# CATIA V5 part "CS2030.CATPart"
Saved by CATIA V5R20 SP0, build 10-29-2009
Part number: CS2030
Revision: 5
Definition: design
Nomenclature: CS2030
Source: made
Description: NOT SPECIFIED
Bounding box of the stored display mesh (mm): x -29 to 29, y -29 to 29, z -55 to 15
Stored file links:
  C:\Users\Raffaele\Desktop\3D X SITO CF\BOLEX\20-TILTED COLUMN SUPPORT\CS2030.CATPart
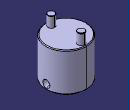
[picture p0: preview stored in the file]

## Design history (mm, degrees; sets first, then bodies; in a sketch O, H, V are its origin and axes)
Body1 "MANIFOLD_SOLID_BREP #715" (main body)
  Solid1: solid without history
